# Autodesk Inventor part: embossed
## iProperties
Shininess: 64.0
Length Units: 11269
Angle Units: 11279
Time Units: 11290
Mass Units: 11283
Length Display Precision: 3
Angle Display Precision: 2
Compacted: True
Part Number: embossed
Document SubType Name: Modeling
Created: 2002-12
Designer: deepak
Density: 1 g/cm^3
Density: 0.0
Volumn: 0.0
Area: 0.0
PropertySet Name: Model Information
Control State: 0
Master: False
Checked Out: False
Author: deepak
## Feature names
1. Extrusion1
2. Extrusion2
